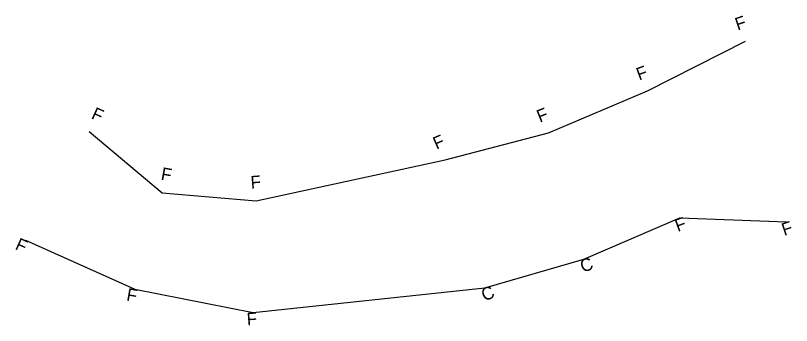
# Model space of a CAD drawing. Extents: x -26 to 2346977, y -10 to 843253.
# Drawn here: x 2346608.6 to 2346977.4, y 843105.6 to 843252.8 of the extents above; entities that cross this region are included whole.
import ezdxf

# ---------------------------------------------------------------- set-up
doc = ezdxf.new("R2010")
doc.units = 0
for name, color, linetype in [('Prop SS Cut Line', 7, 'Continuous'), ('Prop SS Cut Text', 7, 'Continuous'), ('Prop SS Fill Line', 7, 'Continuous'), ('Prop SS Fill Text', 7, 'Continuous'), ('Prop SS Transition Line', 7, 'Continuous')]:
    doc.layers.add(name, color=color, linetype=linetype)

msp = doc.modelspace()

# ---------------------------------------------------------------- linework, layer by layer
at = {"layer": 'Prop SS Cut Line'}
msp.add_line((2346831.73, 843123.51), (2346878.72, 843137.11), dxfattribs=at)
at = {"layer": 'Prop SS Fill Line'}
for p, q in [((2346908.91, 843216.96), (2346955.59, 843240.63)), ((2346861.85, 843197.05), (2346908.91, 843216.96)), ((2346643.57, 843197.77), (2346678.34, 843168.63)), ((2346812.84, 843184.33), (2346861.85, 843197.05)), ((2346722.97, 843164.76), (2346812.84, 843184.33)), ((2346678.34, 843168.63), (2346722.97, 843164.76)), ((2346924.29, 843156.68), (2346975.07, 843154.77)), ((2346613.41, 843146.06), (2346665.27, 843122.82)), ((2346665.27, 843122.82), (2346721.49, 843111.73))]:
    msp.add_line(p, q, dxfattribs=at)
at = {"layer": 'Prop SS Transition Line'}
for p, q in [((2346878.72, 843137.11), (2346924.29, 843156.68)), ((2346721.49, 843111.73), (2346831.73, 843123.51))]:
    msp.add_line(p, q, dxfattribs=at)

# ---------------------------------------------------------------- texts
at = {"layer": 'Prop SS Cut Text'}
for rotation, p in [(18.7815, (2346951.8, 843245.64)), (20.3135, (2346904.99, 843221.87)), (335.749, (2346644.23, 843204.02)), (21.8454, (2346857.8, 843201.86)), (23.3774, (2346808.66, 843189.02)), (350.0729, (2346677.43, 843174.85)), (4.3969, (2346720.55, 843170.56))]:
    msp.add_text('F', height=6, rotation=rotation, dxfattribs=at).set_placement(p)
at = {"layer": 'Prop SS Fill Text'}
for s, rotation, p in [('F', 20.3135, (2346923.34, 843149.96)), ('F', 18.7815, (2346973.93, 843148.08)), ('F', 335.749, (2346608.02, 843141.95)), ('C', 21.8454, (2346878.39, 843130.55)), ('F', 350.0729, (2346661.06, 843117.49)), ('C', 23.3774, (2346831.57, 843116.94)), ('F', 4.3969, (2346718.73, 843105.53))]:
    msp.add_text(s, height=6, rotation=rotation, dxfattribs=at).set_placement(p)

doc.saveas('drawing.dxf')
